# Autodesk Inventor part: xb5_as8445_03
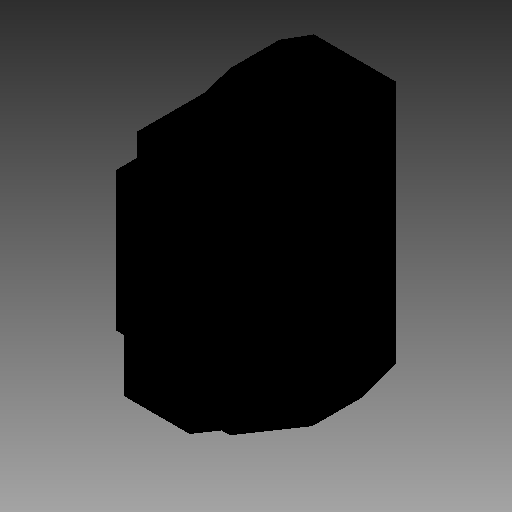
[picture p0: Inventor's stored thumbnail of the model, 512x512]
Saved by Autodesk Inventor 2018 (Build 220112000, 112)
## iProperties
Company: TraceParts S.A.
Created: 2018-04
Part Number: xb5_as8445_03
Checked By: TraceParts S.A.
Material: Generic
Catalog Web Link: www.traceparts.com
Document SubType Name: Modeling
Designer: TraceParts
Density: 1 g/cm^3
Appearance: Default
Author: TraceParts
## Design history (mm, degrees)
feature "xb5_as8445_03.ipt"
body "Solid1"
